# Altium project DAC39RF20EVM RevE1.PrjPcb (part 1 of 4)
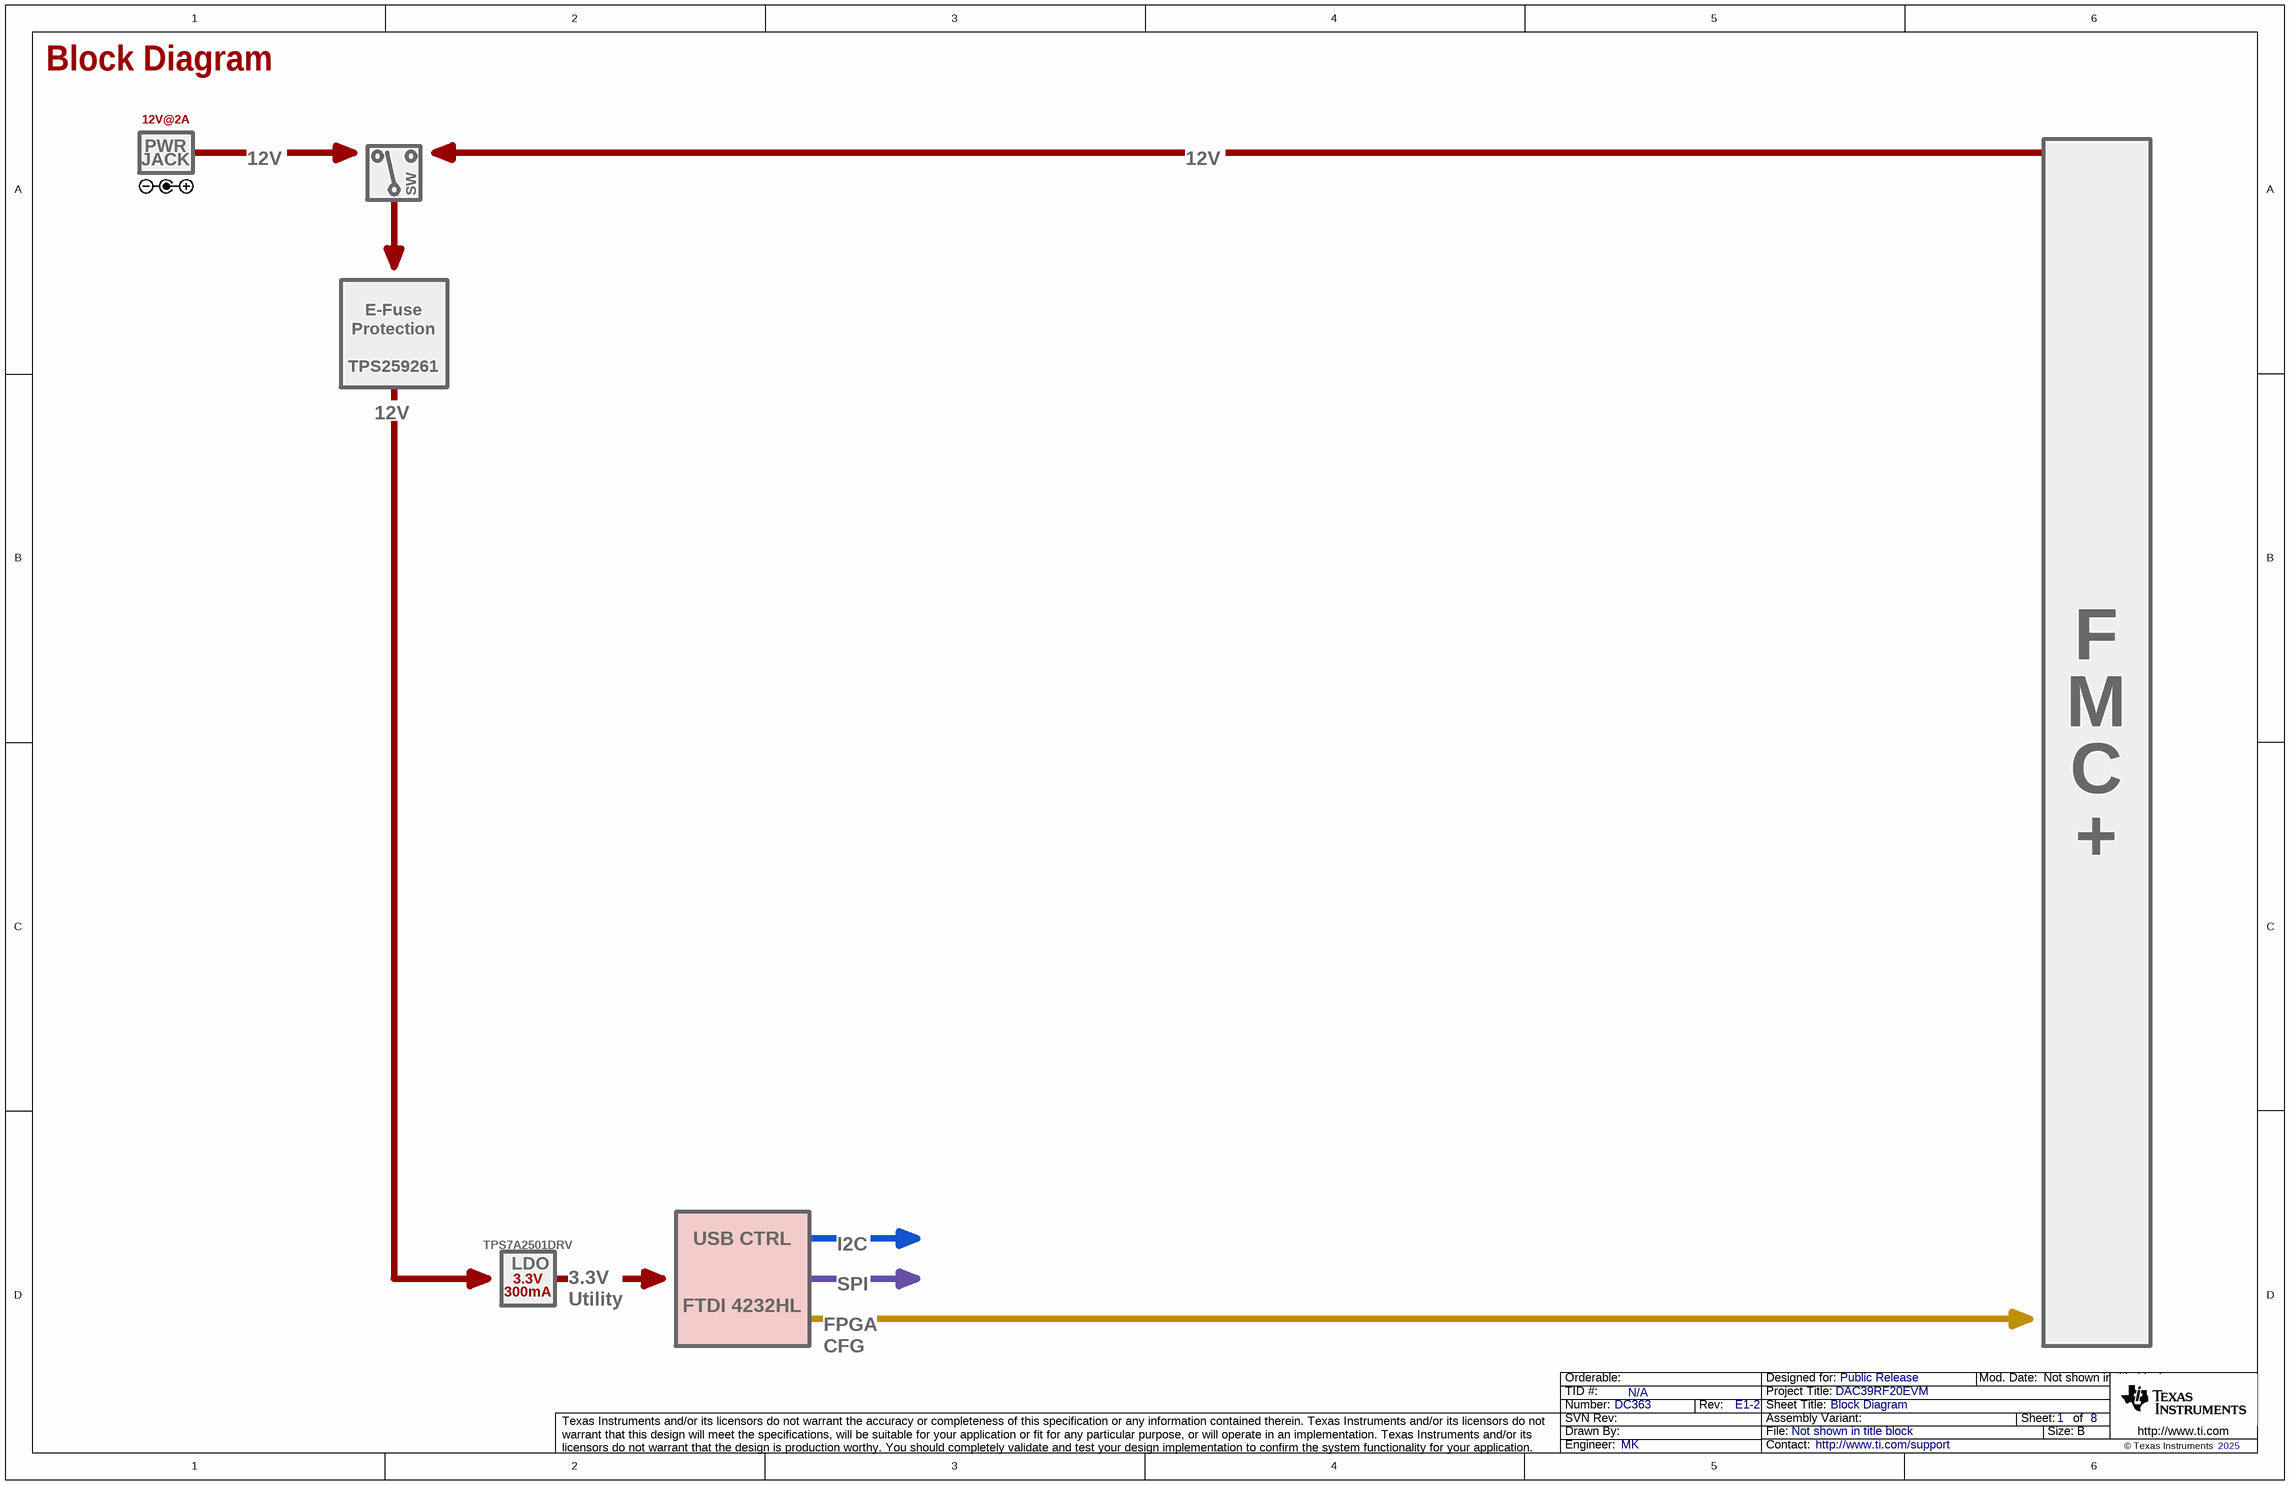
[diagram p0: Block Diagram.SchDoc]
TID: N/A; TechSupport: http://www.ti.com/support; SCH_Rev: E1-2; PRJ_Title: DAC39RF20EVM; PRJ_Number: DC363; PRJ_Engineer: MK; PRJ_Customer: Public Release; PCB_Rev: E1-2; PCB_Layout: GR; CopyrightYear: 2025
21 sheets, 789 parts. Net scope: flat (ports and power ports of the same name join across sheets).
Board file: DAC39RF20EVM.PcbDoc
Sheets:
  Block Diagram.SchDoc
  12V Input, Efuse and 3p3V Utility.SchDoc
  Power Sense ADC.SchDoc
  Power DC-DC Digital.SchDoc
  Power DC-DC Analog.SchDoc
  Power LDO 1p8V Analog.SchDoc
  Power LDO N1p8V Analog.SchDoc
  Power LDO 0p8V Analog.SchDoc
  Power LMK.SchDoc
  USB Control FTDI.SchDoc
  I2C & DAC LVL Shift and MUX.SchDoc
  LMK LVL Shift and Mux.SchDoc
  Clocking LMK04828.SchDoc
  DUT IO.SchDoc
  DUT Outputs.SchDoc
  DUT Power.SchDoc
  FMC+ Sections A-E.SchDoc
  FMC+ Sections F-H, J, K.SchDoc
  FMC+ Sections Y, Z, L, M.SchDoc
  Hardware & Mechanicals.SchDoc
  Revision History.SchDoc

## Sheet Block Diagram.SchDoc: Block Diagram
size 431 x 279 mm; Date: Not shown in title block; ApprovedBy: Not shown in title block; CheckedBy: Not shown in title block; Author: Not shown in title block; CompanyName: Not shown in title block; Engineer: Not shown in title block; Organization: Not shown in title block; Address1: Not shown in title block; Address2: Not shown in title block; Address3: Not shown in title block; Address4: Not shown in title block; DocumentNumber: 1; Revision: Use project parameter SCH_Rev; SheetNumber: 1; SheetTotal: 8; PageSetup: Record=PageOptions¦CenterHorizontal=True¦CenterVertical=True¦PrintScale=1.00¦XCorrection=1.00¦YCorrection=1.00¦PrintKind=0¦BorderSize=5000000¦LeftOffset=0¦BottomOffset=0¦Orientation=2¦PaperLength=1000¦PaperWidth=1000¦Scale=100¦PaperSource=15¦PrintQuality=600¦MediaType=1¦DitherType=10¦PaperKind=Letter¦PrintScaleMode=1

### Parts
(Parts that share a designator on the sheet are numbered #1, #2 ... from top to bottom, then left to right.)
*#1  FMC+  (value not drawn)  (graphical)
*#2  FTDI 4232HL  (value not drawn)  (graphical)
*?#1  PartNum: 12V@2A  (hidden comment: Power Jack)  (graphical)
*?#2  SWITCH  (value not drawn)  (graphical)
*?#3  E-Fuse  (value not drawn)  (graphical)
*?#4  A_Value: 300mA  V_Value: 3.3V  PartNum: TPS7A2501DRV  (hidden comment: LDO)  (graphical)

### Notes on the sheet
- 12V
- I2C
- SPI
- (near *?#4) 3.3V
  Utility
- FPGA
  CFG

## Sheet 12V Input, Efuse and 3p3V Utility.SchDoc: 12V Input & 3.3V Utility
size 431 x 279 mm; Date: Not shown in title block; ApprovedBy: Not shown in title block; CheckedBy: Not shown in title block; Author: Not shown in title block; CompanyName: Not shown in title block; Engineer: Not shown in title block; Organization: Not shown in title block; Address1: Not shown in title block; Address2: Not shown in title block; Address3: Not shown in title block; Address4: Not shown in title block; DocumentNumber: 1; Revision: Use project parameter SCH_Rev; SheetNumber: 2; SheetTotal: 21; PageSetup: Record=PageOptions¦CenterHorizontal=True¦CenterVertical=True¦PrintScale=1.00¦XCorrection=1.00¦YCorrection=1.00¦PrintKind=0¦BorderSize=5000000¦LeftOffset=0¦BottomOffset=0¦Orientation=2¦PaperLength=1000¦PaperWidth=1000¦Scale=100¦PaperSource=15¦PrintQuality=600¦MediaType=1¦DitherType=10¦PaperKind=Letter¦PrintScaleMode=1
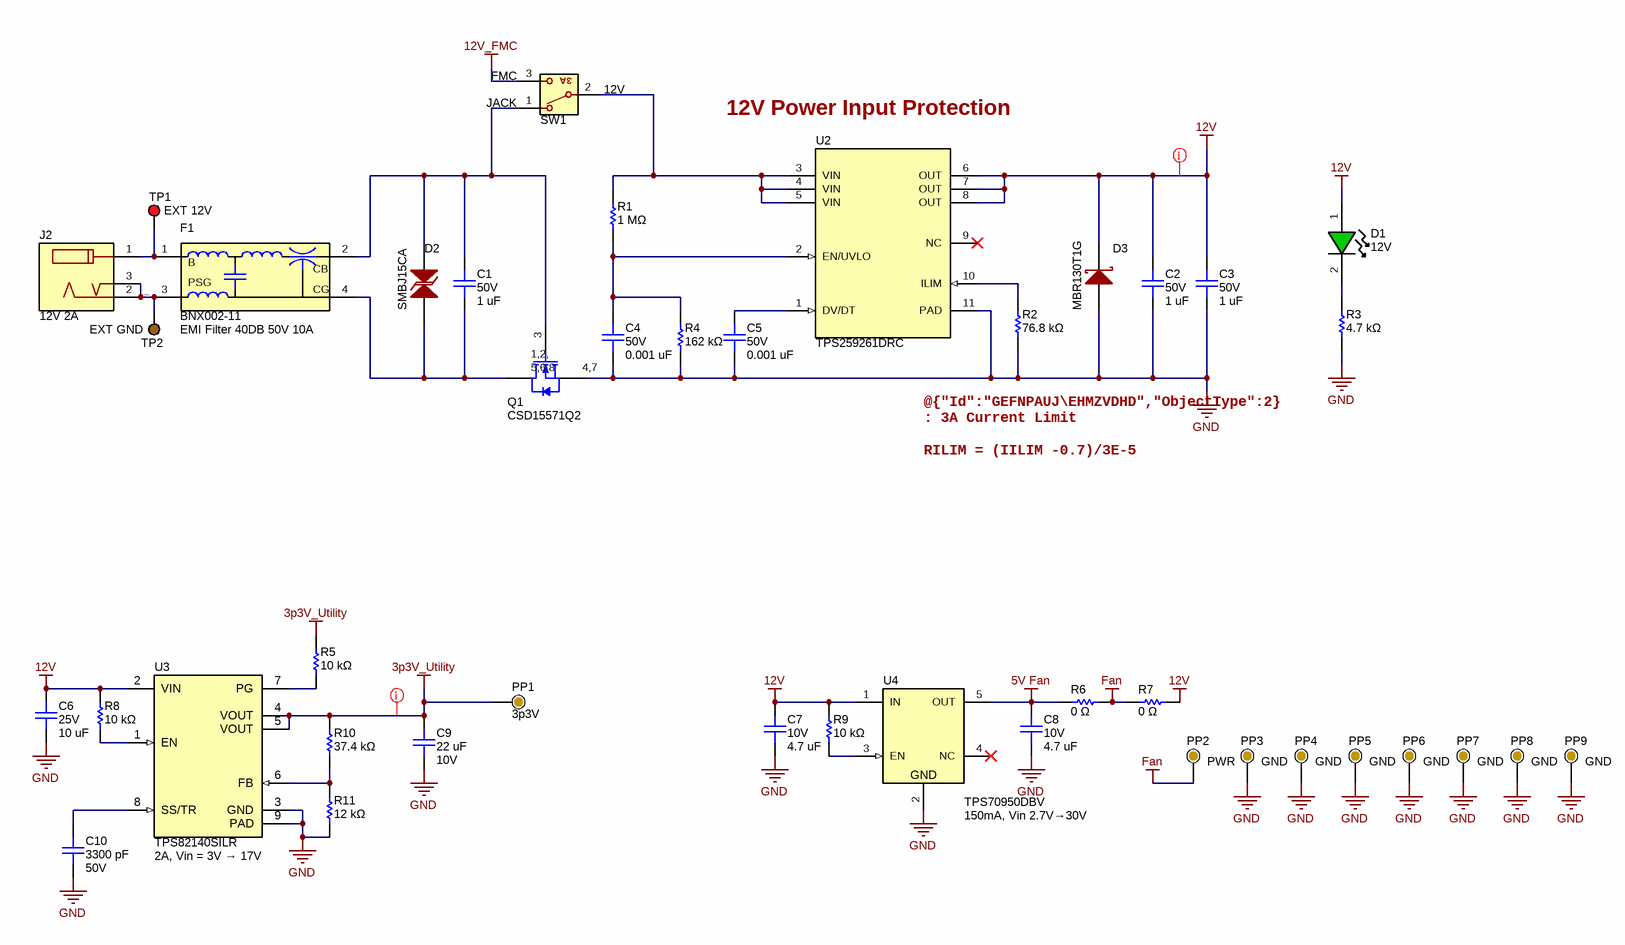
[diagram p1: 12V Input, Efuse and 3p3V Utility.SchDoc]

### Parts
C1  value 1 uF  Voltage - Rated: 50V  [0805L_cap]  (hidden comment: C2012X7R1H105K125AB)
C2  value 1 uF  Voltage - Rated: 50V  [0805L_cap]  (hidden comment: C2012X7R1H105K125AB)
C3  value 1 uF  Voltage - Rated: 50V  [0805L_cap]  (hidden comment: C2012X7R1H105K125AB)
C4  value 0.001 uF  Voltage - Rated: 50V  [0603L_cap]  (hidden comment: CGA3E2X7R1H102K080AA)
C5  value 0.001 uF  Voltage - Rated: 50V  [0603L_cap]  (hidden comment: CGA3E2X7R1H102K080AA)
C6  value 10 uF  Voltage - Rated: 25V  [0805L_cap]  (hidden comment: 08053D106KAT4A)
C7  value 4.7 uF  Voltage - Rated: 10V  [0402L_cap]  (hidden comment: C1005X5R1A475K050BC)
C8  value 4.7 uF  Voltage - Rated: 10V  [0402L_cap]  (hidden comment: C1005X5R1A475K050BC)
C9  value 22 uF  Voltage - Rated: 10V  [0805L_cap]  (hidden comment: C2012X7S1A226M125AC)
C10  value 3300 pF  Voltage - Rated: 50V  [0402L_cap]  (hidden comment: CGA2B2X7R1H332K050BA)
D1  Text1: 12V  [LED_LTST-C190-Green]  (hidden comment: LTST-C191TGKT)
D2  SMBJ15CA  [SMBJ15CA]
D3  MBR130T1G  [SOD-123]
F1  BNX002-11  Text1: EMI Filter 40DB 50V 10A  [FIL_BNX002-11]
J2  Text1: 12V 2A  [RAPC722X]  (hidden comment: RAPC722X)
PP1  Text1: 3p3V  [ProbePoint_TH_40mil]  (hidden comment: Probe Point)  (no BOM)
PP2  Text1: PWR  [ProbePoint_TH_40mil]  (hidden comment: Probe Point)  (no BOM)
PP3  Text1: GND  [ProbePoint_TH_40mil]  (hidden comment: Probe Point)  (no BOM)
PP4  Text1: GND  [ProbePoint_TH_40mil]  (hidden comment: Probe Point)  (no BOM)
PP5  Text1: GND  [ProbePoint_TH_40mil]  (hidden comment: Probe Point)  (no BOM)
PP6  Text1: GND  [ProbePoint_TH_40mil]  (hidden comment: Probe Point)  (no BOM)
PP7  Text1: GND  [ProbePoint_TH_40mil]  (hidden comment: Probe Point)  (no BOM)
PP8  Text1: GND  [ProbePoint_TH_40mil]  (hidden comment: Probe Point)  (no BOM)
PP9  Text1: GND  [ProbePoint_TH_40mil]  (hidden comment: Probe Point)  (no BOM)
Q1  CSD15571Q2  [DQK0006C]
R1  value 1 MΩ  [0402L]  (hidden comment: ERJ-2RKF1004X)
R2  value 76.8 kΩ  [0402L]  (hidden comment: ERJ-2RKF7682X)
R3  value 4.7 kΩ  [0805L]  (hidden comment: ERJ-6ENF4701V)
R4  value 162 kΩ  [0402L]  (hidden comment: ERJ-2RKF1623X)
R5  value 10 kΩ  [0402L]  (hidden comment: ERJ-2RKF1002X)
R6  value 0 Ω  [0805L]  (hidden comment: ERJ-6GEY0R00V)
R7  value 0 Ω  [0805L]  (hidden comment: ERJ-6GEY0R00V)
R8  value 10 kΩ  [0402L]  (hidden comment: ERJ-2RKF1002X)
R9  value 10 kΩ  [0402L]  (hidden comment: ERJ-2RKF1002X)
R10  value 37.4 kΩ  [0402L]  (hidden comment: ERA-2AEB3742X)
R11  value 12 kΩ  [0402L]  (hidden comment: ERJ-2RKF1202X)
SW1  Text1: JACK  Text2: 12V  Text3: FMC  [500ASSP1M2QE]  (hidden comment: 500ASSP1M2QE)
TP1  Text1: EXT 12V  [Keystone5010]  (hidden comment: 5010)
TP2  Text1: EXT GND  [Keystone5125]  (hidden comment: 5125)
U2  TPS259261DRC  [DRC0010J]
U3  TPS82140SILR  Text1: 2A, Vin = 3V → 17V  [SIL0008D]
U4  TPS70950DBV  Text1: 150mA, Vin 2.7V→30V  [DBV0005A]

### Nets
3p3V_Utility: C9.2 PP1.1 R5.2 R10.2 U3.4(VOUT) U3.5(VOUT)
5V Fan: C8.2 R6.2 U4.5(OUT)
12V: C2.2 C3.2 C6.2 C7.2 D1.1(A) D3.1(K) R7.1 R8.2 R9.2 U2.6(OUT) U2.7(OUT) U2.8(OUT) U3.2(VIN) U4.1(IN)
12V_FMC: SW1.3
Fan: PP2.1 R6.1 R7.2
GND: C2.1 C3.1 C4.1 C5.1 C6.1 C7.1 C8.1 C9.1 C10.1 D3.2(A) PP3.1 PP4.1 PP5.1 PP6.1 PP7.1 PP8.1 PP9.1 Q1.4,7(S) R2.1 R3.1 R4.1 R11.1 U2.11(PAD) U3.3(GND) U3.9(PAD) U4.2(GND)
EXTGND: F1.3(PSG) J2.2 J2.3 TP2.1
NetC1_1: C1.1 D2.2 F1.2(CB) Q1.3(G) SW1.1
NetC1_2: C1.2 D2.1 F1.4(CG) Q1.1,2,5,6,8(D)
NetC4_2: C4.2 R1.1 R4.2 U2.2(EN/UVLO)
NetC5_2: C5.2 U2.1(DV/DT)
NetC10_2: C10.2 U3.8(SS/TR)
NetD1_2: D1.2(K) R3.2
NetF1_1: F1.1(B) J2.1 TP1.1
NetR1_2: R1.2 SW1.2(COMM) U2.3(VIN) U2.4(VIN) U2.5(VIN)
NetR2_2: R2.2 U2.10(ILIM)
NetR5_1: R5.1 U3.7(PG)
NetR8_1: R8.1 U3.1(EN)
NetR9_1: R9.1 U4.3(EN)
NetR10_1: R10.1 R11.2 U3.6(FB)

Not connected (* = marked no-connect by the designer): U2 9(NC)*; U4 4(NC)*

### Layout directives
net class Power; net class GenPwr: 3p3V_Utility, 12V

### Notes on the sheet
- 12V Power Input Protection
- @{"Id":"GEFNPAUJ\EHMZVDHD","ObjectType":2} : 3A Current Limit
  RILIM = (IILIM -0.7)/3E-5

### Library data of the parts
C1-C3 = capcc02687: CAP CER 1UF 50V X7R 0805; Manufacturer: TDK Corporation; CompType: Capacitor Ceramic; Tolerance: ±10%; SizeX_mm: 2; SizeY_mm: 1.25; SizeZ_mm: 1.45
C4 C5 = capcc03751: CAP CER 1000PF 50V X7R 0603; Manufacturer: TDK Corporation; CompType: Capacitor Ceramic; Tolerance: ±10%; SizeX_mm: 1.6; SizeY_mm: 0.8; SizeZ_mm: 0.9
C6 = capcc03515: CAP CER 10UF 25V X5R 0805; Manufacturer: KYOCERA AVX; CompType: Capacitor Ceramic; Tolerance: ±10%; SizeX_mm: 2.01; SizeY_mm: 1.25; SizeZ_mm: 1.52
C7 C8 = capcc03298: CAP CER 4.7UF 10V X5R 0402; Manufacturer: TDK Corporation; CompType: Capacitor Ceramic; Tolerance: ±10%; SizeX_mm: 1; SizeY_mm: 0.5; SizeZ_mm: 0.65
C9 = capcc09395: CAP CER 22UF 10V X7S 0805; Manufacturer: TDK Corporation; CompType: Capacitor Ceramic; Tolerance: ±20%; SizeX_mm: 2; SizeY_mm: 1.25; SizeZ_mm: 1.45
C10 = capcc04738: CAP CER 3300PF 50V X7R 0402; Manufacturer: TDK Corporation; CompType: Capacitor Ceramic; Tolerance: ±10%; SizeX_mm: 1; SizeY_mm: 0.5; SizeZ_mm: 0.55
D1 = cmp00247: LED GREEN CLEAR CHIP SMD; Manufacturer: Lite-On Inc.; Current Rating (Amps): 20mA; Voltage - Forward (Vf) (Typ): 3.2V; SizeX_mm: 1.6; SizeY_mm: 0.8; SizeZ_mm: 0.65
D2 = cmp00440: 24.4V Clamp 24.6A Ipp Tvs Diode; Manufacturer: Littlefuse; CompType: Diode TVS
D3 = cmp00438: DIODE SCHOTTKY 30V 1A SOD123; Manufacturer: Onsemi; Alt PartNumber: RB160M-30TR; Alt Manufacturer: Rohm Semiconductor
F1 = cmp00325: EMI Filter Circuits 40 DB 50V 10A; Manufacturer: Murata Electronics
J2 = cmp00022: Power Jack, mini, 2.1mm OD, R/A, TH; Manufacturer: Switchcraft
PP1-PP9 = Probe Point: Probe Point that can be used in lue of a test point; UniqueID: cmp00025
Q1 = cmp00159: MOSFET, N-CH, 20 V, 10 A; Manufacturer: Texas Instruments; CompType: FET
R1 = RSMD040200026: RES SMD 1M OHM 1% 1/10W 0402; Manufacturer: Panasonic Electronic Components; CompType: Resistor SMD; Power (Watts): 0.1W, 1/10W; Temperature Coefficient: ±100ppm/°C; SizeX_mm: 1; SizeY_mm: 0.5; SizeZ_mm: 0.4
R2 = RSMD040203665: RES SMD 76.8K OHM 1% 1/10W 0402; Manufacturer: Panasonic Electronic Components; CompType: Resistor SMD; Power (Watts): 0.1W, 1/10W; Temperature Coefficient: ±100ppm/°C; SizeX_mm: 1; SizeY_mm: 0.5; SizeZ_mm: 0.4
R3 = RSMD080501129: RES SMD 4.7K OHM 1% 1/8W 0805; Manufacturer: Panasonic Electronic Components; CompType: Resistor SMD; Power (Watts): 0.125W, 1/8W; Temperature Coefficient: ±100ppm/°C; SizeX_mm: 2; SizeY_mm: 1.25; SizeZ_mm: 0.7
R4 = RSMD040200945: RES SMD 162K OHM 1% 1/10W 0402; Manufacturer: Panasonic Electronic Components; CompType: Resistor SMD; Power (Watts): 0.1W, 1/10W; Temperature Coefficient: ±100ppm/°C; SizeX_mm: 1; SizeY_mm: 0.5; SizeZ_mm: 0.4
R5 R8 R9 = RSMD040200314: RES SMD 10K OHM 1% 1/10W 0402; Manufacturer: Panasonic Electronic Components; CompType: Resistor SMD; Power (Watts): 0.1W, 1/10W; Temperature Coefficient: ±100ppm/°C; SizeX_mm: 1; SizeY_mm: 0.5; SizeZ_mm: 0.4
R6 R7 = RSMD080510615: RES SMD 0 OHM JUMPER 1/8W 0805; Manufacturer: Panasonic Electronic Components; CompType: Resistor SMD; Power (Watts): 0.125W, 1/8W; SizeX_mm: 2; SizeY_mm: 1.25; SizeZ_mm: 0.7
R10 = RSMD040202418: RES SMD 37.4KOHM 0.1% 1/16W 0402; Manufacturer: Panasonic Electronic Components; CompType: Resistor SMD; Power (Watts): 0.063W, 1/16W; Temperature Coefficient: ±25ppm/°C; SizeX_mm: 1; SizeY_mm: 0.5; SizeZ_mm: 0.4
R11 = RSMD040200519: RES SMD 12K OHM 1% 1/10W 0402; Manufacturer: Panasonic Electronic Components; CompType: Resistor SMD; Power (Watts): 0.1W, 1/10W; Temperature Coefficient: ±100ppm/°C; SizeX_mm: 1; SizeY_mm: 0.5; SizeZ_mm: 0.4
SW1 = cmp00460: SWITCH SLIDE SPDT 3A 120V; Manufacturer: E-Switch; Pitch (mm): 2.54
TP1 = cmp00040: Test Point, Multipurpose, Red, TH; Manufacturer: Keystone
TP2 = cmp00047: Test Point, Multipurpose, Brown, TH; Manufacturer: Keystone
U2 = cmp00157: 12V, 5A, 30mΩ eFuse with Adjustable +/-15% Accurate Current Limit, DRC0010J (VSON-10); Manufacturer: Texas Instruments
U3 = TPS82140SILR: 17V Input 2A Synchronous Step-Down Converter MicroSiP Module With Integrated Inductor, SIL0008D (uSIP-8); Manufacturer: Texas Instruments; Alternate PartNumber: TPS82140SILT; CompType: Switcher
U4 = TPS70950DBV: 150-mA, 30-V, ultra-low-IQ, low-dropout voltage regulator with reverse current protection and enable; Manufacturer: Texas Instruments; CompType: LDO

## Sheet Power Sense ADC.SchDoc: Sense ADC
size 431 x 279 mm; Date: Not shown in title block; ApprovedBy: Not shown in title block; CheckedBy: Not shown in title block; Author: Not shown in title block; CompanyName: Not shown in title block; Engineer: Not shown in title block; Organization: Not shown in title block; Address1: Not shown in title block; Address2: Not shown in title block; Address3: Not shown in title block; Address4: Not shown in title block; DocumentNumber: 1; Revision: Use project parameter SCH_Rev; SheetNumber: 3; SheetTotal: 21; PageSetup: Record=PageOptions¦CenterHorizontal=True¦CenterVertical=True¦PrintScale=1.00¦XCorrection=1.00¦YCorrection=1.00¦PrintKind=0¦BorderSize=5000000¦LeftOffset=0¦BottomOffset=0¦Orientation=2¦PaperLength=1000¦PaperWidth=1000¦Scale=100¦PaperSource=15¦PrintQuality=600¦MediaType=1¦DitherType=10¦PaperKind=Letter¦PrintScaleMode=1
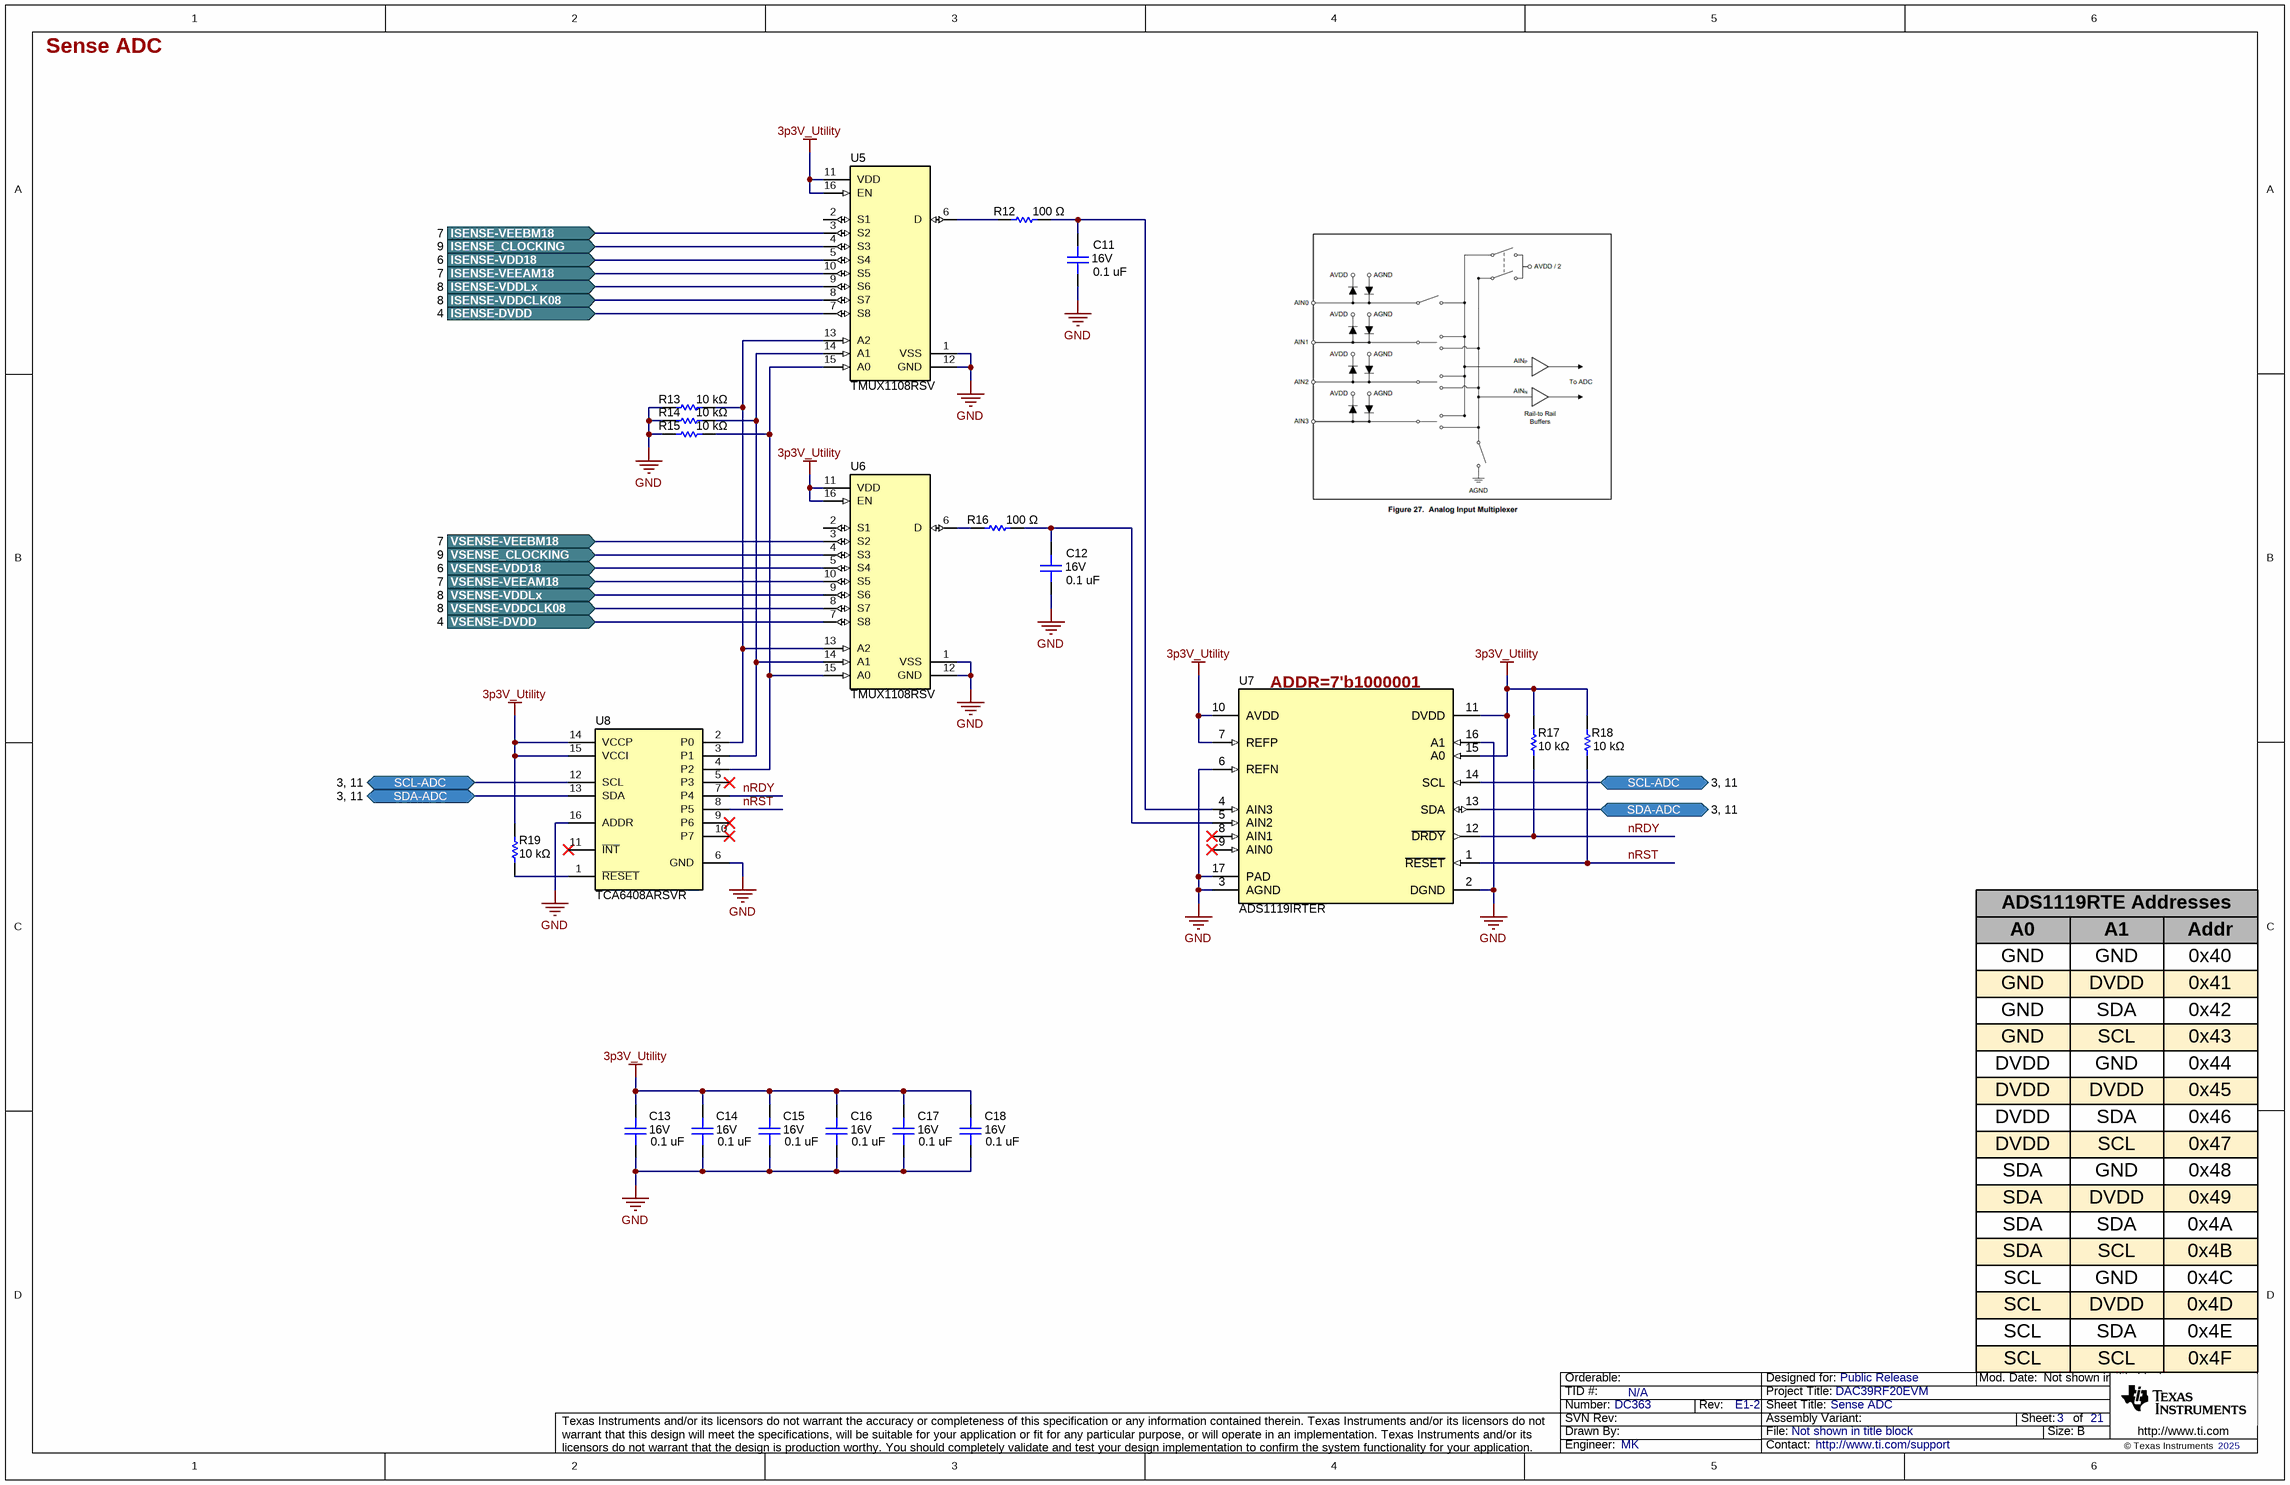
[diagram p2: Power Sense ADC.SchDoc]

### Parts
C11  value 0.1 uF  Voltage - Rated: 16V  [0201_cap]  (hidden comment: C0603X5R1C104K030BC)
C12  value 0.1 uF  Voltage - Rated: 16V  [0201_cap]  (hidden comment: C0603X5R1C104K030BC)
C13  value 0.1 uF  Voltage - Rated: 16V  [0201_cap]  (hidden comment: C0603X5R1C104K030BC)
C14  value 0.1 uF  Voltage - Rated: 16V  [0201_cap]  (hidden comment: C0603X5R1C104K030BC)
C15  value 0.1 uF  Voltage - Rated: 16V  [0201_cap]  (hidden comment: C0603X5R1C104K030BC)
C16  value 0.1 uF  Voltage - Rated: 16V  [0201_cap]  (hidden comment: C0603X5R1C104K030BC)
C17  value 0.1 uF  Voltage - Rated: 16V  [0201_cap]  (hidden comment: C0603X5R1C104K030BC)
C18  value 0.1 uF  Voltage - Rated: 16V  [0201_cap]  (hidden comment: C0603X5R1C104K030BC)
R12  value 100 Ω  [0201]  (hidden comment: ERJ-1GNF1000C)
R13  value 10 kΩ  [0201]  (hidden comment: ERJ-1GNF1002C)
R14  value 10 kΩ  [0201]  (hidden comment: ERJ-1GNF1002C)
R15  value 10 kΩ  [0201]  (hidden comment: ERJ-1GNF1002C)
R16  value 100 Ω  [0201]  (hidden comment: ERJ-1GNF1000C)
R17  value 10 kΩ  [0201]  (hidden comment: ERJ-1GNF1002C)
R18  value 10 kΩ  [0201]  (hidden comment: ERJ-1GNF1002C)
R19  value 10 kΩ  [0201]  (hidden comment: ERJ-1GNF1002C)
U5  TMUX1108RSVR  [RSV0016A]  (value not drawn)
U6  TMUX1108RSVR  [RSV0016A]  (value not drawn)
U7  ADS1119IRTET  [RTE0016D]  (value not drawn)
U8  TCA6408ARSVR  [RSV0016A]

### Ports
ISENSE-DVDD (in, see 4), ISENSE-VDD18 (in, see 6), ISENSE-VDDCLK08 (in, see 8), ISENSE-VDDLx (in, see 8), ISENSE-VEEAM18 (in, see 7), ISENSE-VEEBM18 (in, see 7), ISENSE_CLOCKING (in, see 9), SCL-ADC (bidir, see 3, 11), SDA-ADC (bidir, see 3, 11), VSENSE-DVDD (in, see 4), VSENSE-VDD18 (in, see 6), VSENSE-VDDCLK08 (in, see 8), VSENSE-VDDLx (in, see 8), VSENSE-VEEAM18 (in, see 7), VSENSE-VEEBM18 (in, see 7), VSENSE_CLOCKING (in, see 9)

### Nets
3p3V_Utility: C13.1 C14.1 C15.1 C16.1 C17.1 C18.1 R17.2 R18.2 R19.2 U5.11(VDD) U5.16(EN) U6.11(VDD) U6.16(EN) U7.7(REFP) U7.10(AVDD) U7.11(DVDD) U7.15(A0) U8.14(VCCP) U8.15(VCCI)
GND: C11.2 C12.2 C13.2 C14.2 C15.2 C16.2 C17.2 C18.2 R13.2 R14.2 R15.2 U5.1(VSS) U5.12(GND) U6.1(VSS) U6.12(GND) U7.2(DGND) U7.3(AGND) U7.6(REFN) U7.16(A1) U7.17(PAD) U8.6(GND) U8.16(ADDR)
ISENSE-DVDD: U5.7(S8) ; port ISENSE-DVDD
ISENSE-VDD18: U5.5(S4) ; port ISENSE-VDD18
ISENSE-VDDCLK08: U5.8(S7) ; port ISENSE-VDDCLK08
ISENSE-VDDLx: U5.9(S6) ; port ISENSE-VDDLx
ISENSE-VEEAM18: U5.10(S5) ; port ISENSE-VEEAM18
ISENSE-VEEBM18: U5.3(S2) ; port ISENSE-VEEBM18
ISENSE_CLOCKING: U5.4(S3) ; port ISENSE_CLOCKING
nRDY: R17.1 U7.12(~{DRDY}) U8.7(P4)
nRST: R18.1 U7.1(~{RESET}) U8.8(P5)
SCL-ADC: U7.14(SCL) U8.12(SCL) ; port SCL-ADC
SDA-ADC: U7.13(SDA) U8.13(SDA) ; port SDA-ADC
VSENSE-DVDD: U6.7(S8) ; port VSENSE-DVDD
VSENSE-VDD18: U6.5(S4) ; port VSENSE-VDD18
VSENSE-VDDCLK08: U6.8(S7) ; port VSENSE-VDDCLK08
VSENSE-VDDLx: U6.9(S6) ; port VSENSE-VDDLx
VSENSE-VEEAM18: U6.10(S5) ; port VSENSE-VEEAM18
VSENSE-VEEBM18: U6.3(S2) ; port VSENSE-VEEBM18
VSENSE_CLOCKING: U6.4(S3) ; port VSENSE_CLOCKING
NetC11_1: C11.1 R12.2 U7.4(AIN3)
NetC12_1: C12.1 R16.2 U7.5(AIN2)
NetR12_1: R12.1 U5.6(D)
NetR13_1: R13.1 U5.13(A2) U6.13(A2) U8.2(P0)
NetR14_1: R14.1 U5.14(A1) U6.14(A1) U8.3(P1)
NetR15_1: R15.1 U5.15(A0) U6.15(A0) U8.4(P2)
NetR16_1: R16.1 U6.6(D)
NetR19_1: R19.1 U8.1(~{RESET})

Not connected (* = marked no-connect by the designer): U5 2(S1); U6 2(S1); U7 8(AIN1)* 9(AIN0)*; U8 5(P3)* 9(P6)* 10(P7)* 11(~{INT})*

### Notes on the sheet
- (near U7) ADDR=7'b1000001
- A0
- GND
- ADS1119RTE Addresses
- A1
- Addr
- 0x40
- DVDD
- SDA
- 0x41
- 0x42
- SCL
- 0x43
- 0x44
- 0x45
- 0x46
- 0x47
- 0x48
- 0x49
- 0x4A
- 0x4B
- 0x4C
- 0x4D
- 0x4E
- 0x4F

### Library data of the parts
C11-C18 = capcc01389: CAP CER 0.1UF 16V X5R 0201; Manufacturer: TDK Corporation; SizeZ_mm: 0.33; SizeY_mm: 0.3; CompType: Capacitor Ceramic; SizeX_mm: 0.6; Tolerance: ±10%
R12 R16 = RSMD020100289: RES SMD 100 OHM 1% 1/20W 0201; Manufacturer: Panasonic Electronic Components; CompType: Resistor SMD; Power (Watts): 0.05W, 1/20W; Temperature Coefficient: ±200ppm/°C
R13-R15 R17-R19 = RSMD020100762: RES SMD 10K OHM 1% 1/20W 0201; Manufacturer: Panasonic Electronic Components; CompType: Resistor SMD; Power (Watts): 0.05W, 1/20W; Temperature Coefficient: ±200ppm/°C
U5 U6 = TMUX1108RSV: 3-pA on-state leakage current, 5-V, 8:1, 1-channel precision multiplexer; Manufacturer: Texas Instruments; CompType: MUX; SizeZ_mm: .55; SizeY_mm: 2.6; SizeX_mm: 1.8
U7 = ADS1119IRTER: 16-Bit, 4-Channel, 1-kSPS, Delta-Sigma ADC with I2C Interface, RTE0016D (WQFN-16); Alternate Manufacturer: Texas Instruments; SizeAreaWB_mm2: 16; SizeZ_mm: 0.8; SizeX_mm: 3; SizeArea_mm2: 9; AEC Qualified: N; AEC Category: Q200
U8 = cmp00387: 8-bit translating 1.65- to 5.5-V I2C/SMBus I/O expander with interrupt, reset & config registers; Manufacturer: Texas Instruments; CompType: IO Expander

## Sheet Power DC-DC Digital.SchDoc: DAC DVDD Rail
size 431 x 279 mm; Date: Not shown in title block; ApprovedBy: Not shown in title block; CheckedBy: Not shown in title block; Author: Not shown in title block; CompanyName: Not shown in title block; Engineer: Not shown in title block; Organization: Not shown in title block; Address1: Not shown in title block; Address2: Not shown in title block; Address3: Not shown in title block; Address4: Not shown in title block; DocumentNumber: 1; Revision: Use project parameter SCH_Rev; SheetNumber: 4; SheetTotal: 21; PageSetup: Record=PageOptions¦CenterHorizontal=True¦CenterVertical=True¦PrintScale=1.00¦XCorrection=1.00¦YCorrection=1.00¦PrintKind=0¦BorderSize=5000000¦LeftOffset=0¦BottomOffset=0¦Orientation=2¦PaperLength=1000¦PaperWidth=1000¦Scale=100¦PaperSource=15¦PrintQuality=600¦MediaType=1¦DitherType=10¦PaperKind=Letter¦PrintScaleMode=1
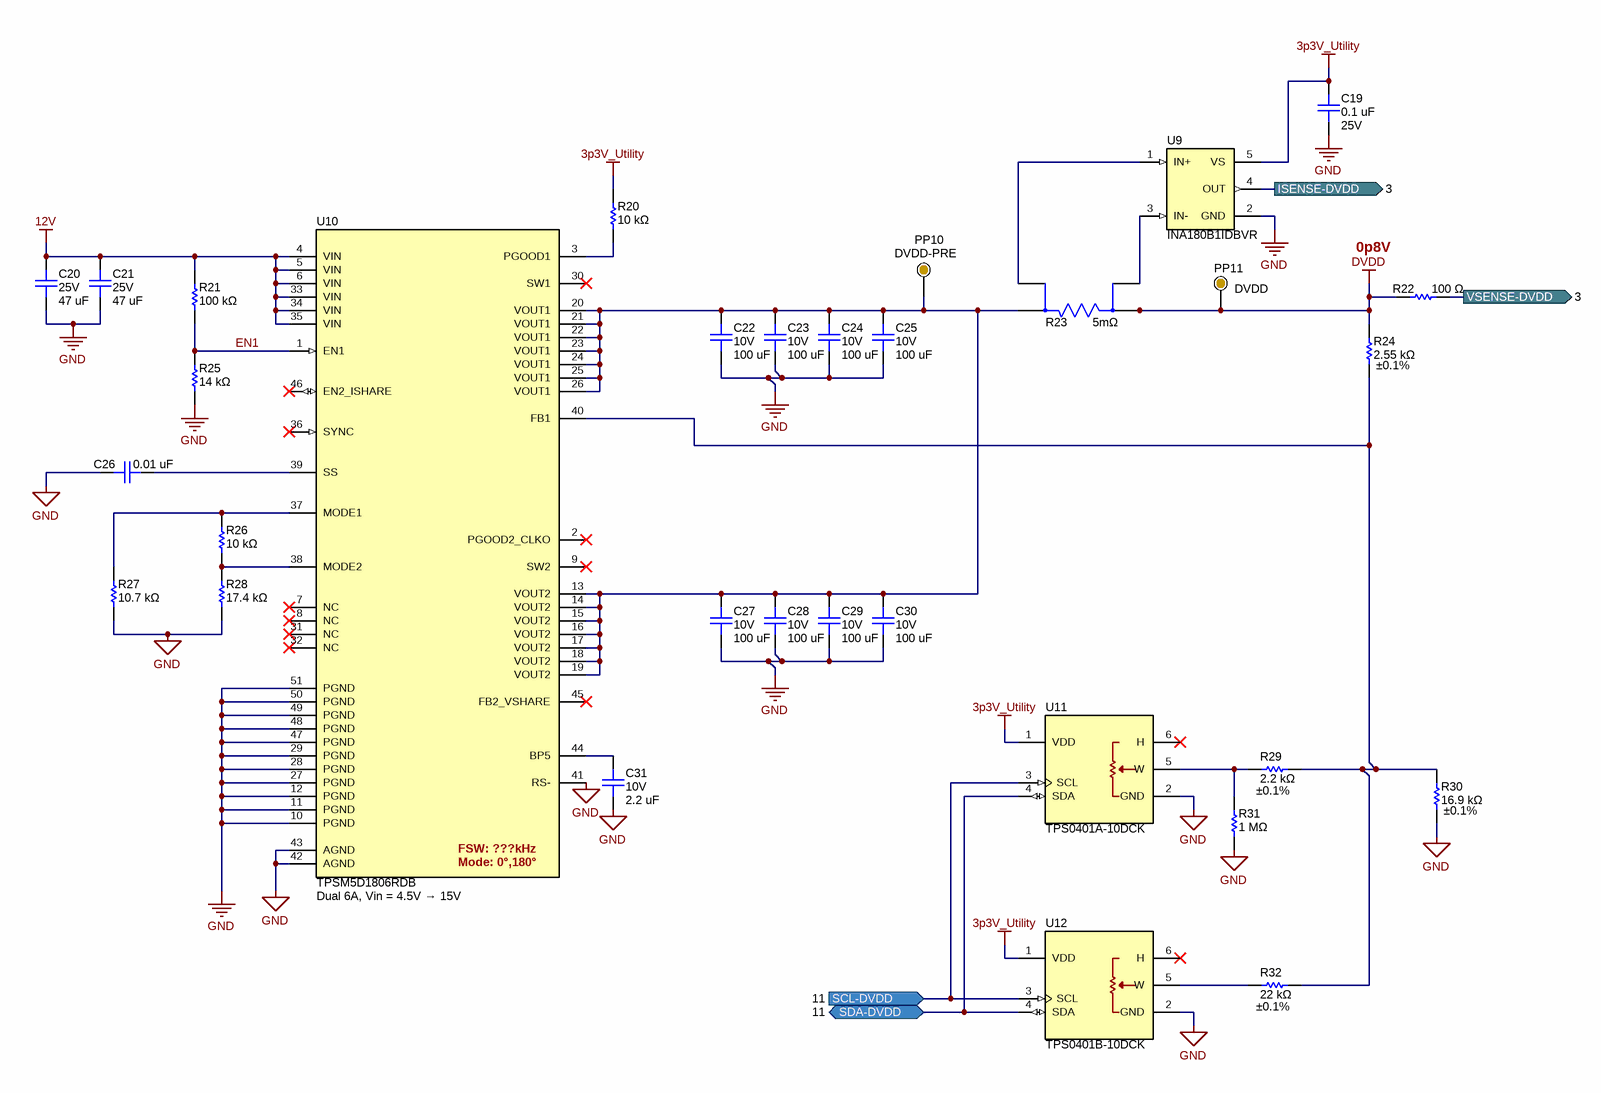
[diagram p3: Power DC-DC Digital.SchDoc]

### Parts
C19  value 0.1 uF  Voltage - Rated: 25V  [0402L_cap]  (hidden comment: GRT155R71E104KE01J)
C20  value 47 uF  Voltage - Rated: 25V  [1206L_cap]  (hidden comment: C3216X5R1E476M160AC)
C21  value 47 uF  Voltage - Rated: 25V  [1206L_cap]  (hidden comment: C3216X5R1E476M160AC)
C22  value 100 uF  Voltage - Rated: 10V  [1206L_cap]  (hidden comment: GMC31X5R107M10NT)
C23  value 100 uF  Voltage - Rated: 10V  [1206L_cap]  (hidden comment: GMC31X5R107M10NT)
C24  value 100 uF  Voltage - Rated: 10V  [1206L_cap]  (hidden comment: GMC31X5R107M10NT)
C25  value 100 uF  Voltage - Rated: 10V  [1206L_cap]  (hidden comment: GMC31X5R107M10NT)
C26  value 0.01 uF  [0402L_cap]  (hidden comment: 0402YD103KAT2A)
C27  value 100 uF  Voltage - Rated: 10V  [1206L_cap]  (hidden comment: GMC31X5R107M10NT)
C28  value 100 uF  Voltage - Rated: 10V  [1206L_cap]  (hidden comment: GMC31X5R107M10NT)
C29  value 100 uF  Voltage - Rated: 10V  [1206L_cap]  (hidden comment: GMC31X5R107M10NT)
C30  value 100 uF  Voltage - Rated: 10V  [1206L_cap]  (hidden comment: GMC31X5R107M10NT)
C31  value 2.2 uF  Voltage - Rated: 10V  [0402L_cap]  (hidden comment: CM05X5R225K10AH)
PP10  Text1: DVDD-PRE  [ProbePoint_TH_40mil]  (hidden comment: Probe Point)  (no BOM)
PP11  Text1: DVDD  [ProbePoint_TH_40mil]  (hidden comment: Probe Point)  (no BOM)
R20  value 10 kΩ  [0402L]  (hidden comment: ERJ-2RKF1002X)
R21  value 100 kΩ  [0402L]  (hidden comment: ERJ-2RKF1003X)
R22  value 100 Ω  [0201]  (hidden comment: ERJ-1GNF1000C)
R23  Res_ohm: 5mΩ  [FP-KRL3216T4A-M-R005-F-T1_1206-MFG]  (hidden comment: KRL3216T4A-M-R005-F-T1)
R24  value 2.55 kΩ  Tolerance: ±0.1%  [0402L]  (hidden comment: ERA-2APB2551X)
R25  value 14 kΩ  [0402L]  (hidden comment: ERJ-2RKF1402X)
R26  value 10 kΩ  [0402L]  (hidden comment: ERJ-2RKF1002X)
R27  value 10.7 kΩ  [0402L]  (hidden comment: ERJ-2RKF1072X)
R28  value 17.4 kΩ  [0402L]  (hidden comment: ERJ-2RKF1742X)
R29  value 2.2 kΩ  Tolerance: ±0.1%  [0402L]  (hidden comment: ERA-2ARB222X)
R30  value 16.9 kΩ  Tolerance: ±0.1%  [0402L]  (hidden comment: ERA-2ARB1692X)
R31  value 1 MΩ  [0402L]  (hidden comment: ERJ-PA2F1004X)
R32  value 22 kΩ  Tolerance: ±0.1%  [0402L]  (hidden comment: ERA-2APB223X)
U9  INA180B1IDBVR  [DBV0005A]
U10  TPSM5D1806RDB  Text1: Dual 6A, Vin = 4.5V → 15V  Mode: 0°,180°  FSW: ???kHz  [RDB0051A]
U11  TPS0401A-10DCK  [DCK0006A]
U12  TPS0401B-10DCK  [DCK0006A]

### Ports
ISENSE-DVDD (out, see 3), SCL-DVDD (in, see 11), SDA-DVDD (bidir, see 11), VSENSE-DVDD (out, see 3)

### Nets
3p3V_Utility: C19.2 R20.2 U9.5(VS) U11.1(VDD) U12.1(VDD)
12V: C20.2 C21.2 R21.2 U10.4(VIN) U10.5(VIN) U10.6(VIN) U10.33(VIN) U10.34(VIN) U10.35(VIN)
DVDD: PP11.1 R22.1 R23.3(1_I) R24.2
GND: C19.1 C20.1 C21.1 C22.1 C23.1 C24.1 C25.1 C26.1 C27.1 C28.1 C29.1 C30.1 C31.1 R25.1 R27.1 R28.1 R30.2 R31.2 U9.2(GND) U10.10(PGND) U10.11(PGND) U10.12(PGND) U10.27(PGND) U10.28(PGND) U10.29(PGND) U10.41(RS-) U10.42(AGND) U10.43(AGND) U10.47(PGND) U10.48(PGND) U10.49(PGND) U10.50(PGND) U10.51(PGND) U11.2(GND) U12.2(GND)
EN1: R21.1 R25.2 U10.1(EN1)
ISENSE-DVDD: U9.4(OUT) ; port ISENSE-DVDD
SCL-DVDD: U11.3(SCL) U12.3(SCL) ; port SCL-DVDD
SDA-DVDD: U11.4(SDA) U12.4(SDA) ; port SDA-DVDD
VSENSE-DVDD: R22.2 ; port VSENSE-DVDD
NetC22_2: C22.2 C23.2 C24.2 C25.2 C27.2 C28.2 C29.2 C30.2 PP10.1 R23.4(2_I) U10.13(VOUT2) U10.14(VOUT2) U10.15(VOUT2) U10.16(VOUT2) U10.17(VOUT2) U10.18(VOUT2) U10.19(VOUT2) U10.20(VOUT1) U10.21(VOUT1) U10.22(VOUT1) U10.23(VOUT1) U10.24(VOUT1) U10.25(VOUT1) U10.26(VOUT1)
NetC26_2: C26.2 U10.39(SS)
NetC31_2: C31.2 U10.44(BP5)
NetR20_1: R20.1 U10.3(PGOOD1)
NetR23_1: R23.1(1_V) U9.3(IN-)
NetR23_2: R23.2(2_V) U9.1(IN+)
NetR24_1: R24.1 R29.2 R30.1 R32.2 U10.40(FB1)
NetR26_1: R26.1 R27.2 U10.37(MODE1)
NetR26_2: R26.2 R28.2 U10.38(MODE2)
NetR29_1: R29.1 R31.1 U11.5(W)
NetR32_1: R32.1 U12.5(W)

Not connected (* = marked no-connect by the designer): U10 2(PGOOD2_CLKO)* 7(NC)* 8(NC)* 9(SW2)* 30(SW1)* 31(NC)* 32(NC)* 36(SYNC)* 45(FB2_VSHARE)* 46(EN2_ISHARE)*; U11 6(H)*; U12 6(H)*

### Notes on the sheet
- (near R22) 0p8V

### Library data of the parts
C19 = capcc09401: CAP CER 0.1UF 25V X7R 0402; Manufacturer: Murata; CompType: Capacitor Ceramic; Tolerance: ±10%; SizeX_mm: 1; SizeY_mm: 0.5; SizeZ_mm: 0.7
C20 C21 = capcc09404: CAP CER 47UF 25V X5R 1206; Manufacturer: TDK Corporation; CompType: Capacitor Ceramic; Tolerance: ±20%; SizeX_mm: 3.2; SizeY_mm: 1.6; SizeZ_mm: 1.8
C22-C25 C27-C30 = capcc06824: CAP CER 100UF 10V X5R 1206; Manufacturer: CAL-CHIP ELECTRONICS, INC.; CompType: Capacitor Ceramic; Tolerance: ±20%; SizeX_mm: 3.2; SizeY_mm: 1.6
C26 = capcc05508: CAP CER 10000PF 16V X5R 0402; Manufacturer: KYOCERA AVX; CompType: Capacitor Ceramic; Tolerance: ±10%; SizeX_mm: 1; SizeY_mm: 0.5; SizeZ_mm: 0.56
C31 = capcc03230: CAP CER 2.2UF 10V X5R 0402; Manufacturer: KYOCERA AVX; CompType: Capacitor Ceramic; Tolerance: ±10%; SizeX_mm: 1; SizeY_mm: 0.5; SizeZ_mm: 0.55
PP10 PP11 = Probe Point: as PP1 on sheet 12V Input, Efuse and 3p3V Utility
R20 R26 = RSMD040200314: as R5 on sheet 12V Input, Efuse and 3p3V Utility
R21 = RSMD040200358: RES SMD 100K OHM 1% 1/10W 0402; Manufacturer: Panasonic Electronic Components; CompType: Resistor SMD; Power (Watts): 0.1W, 1/10W; Temperature Coefficient: ±100ppm/°C; SizeX_mm: 1; SizeY_mm: 0.5; SizeZ_mm: 0.4
R22 = RSMD020100289: as R12 on sheet Power Sense ADC
R23 = CMP-0089456-1: 5 mOhms ±1% 1W Chip Resistor Wide 1206 (3216 Metric), 0612 Automotive AEC-Q200, Current Sense Metal Foil; Manufacturer: Susumu; AEC Grade: Grade 0; SizeZ_mm: 0.7mm; AEC Qualified: Yes; TempCo: 50ppm/°C
R24 = RSMD040201279: RES SMD 2.55KOHM 0.1% 1/16W 0402; Manufacturer: Panasonic Electronic Components; CompType: Resistor SMD; Power (Watts): 0.063W, 1/16W; Temperature Coefficient: ±15ppm/°C; SizeX_mm: 1; SizeY_mm: 0.5; SizeZ_mm: 0.4
R25 = RSMD040200723: RES SMD 14K OHM 1% 1/10W 0402; Manufacturer: Panasonic Electronic Components; CompType: Resistor SMD; Power (Watts): 0.1W, 1/10W; Temperature Coefficient: ±100ppm/°C; SizeX_mm: 1; SizeY_mm: 0.5; SizeZ_mm: 0.4
R27 = RSMD040200350: RES SMD 10.7K OHM 1% 1/10W 0402; Manufacturer: Panasonic Electronic Components; CompType: Resistor SMD; Power (Watts): 0.1W, 1/10W; Temperature Coefficient: ±100ppm/°C; SizeX_mm: 1; SizeY_mm: 0.5; SizeZ_mm: 0.4
R28 = RSMD040200983: RES SMD 17.4K OHM 1% 1/10W 0402; Manufacturer: Panasonic Electronic Components; CompType: Resistor SMD; Power (Watts): 0.1W, 1/10W; Temperature Coefficient: ±100ppm/°C; SizeX_mm: 1; SizeY_mm: 0.5; SizeZ_mm: 0.4
R29 = RSMD040201204: RES SMD 2.2K OHM 0.1% 1/16W 0402; Manufacturer: Panasonic Electronic Components; CompType: Resistor SMD; Power (Watts): 0.063W, 1/16W; Temperature Coefficient: ±10ppm/°C; SizeX_mm: 1; SizeY_mm: 0.5; SizeZ_mm: 0.4
R30 = RSMD040200908: RES SMD 16.9KOHM 0.1% 1/16W 0402; Manufacturer: Panasonic Electronic Components; CompType: Resistor SMD; Power (Watts): 0.063W, 1/16W; Temperature Coefficient: ±10ppm/°C; SizeX_mm: 1; SizeY_mm: 0.5; SizeZ_mm: 0.4
R31 = RSMD040200022: RES SMD 1M OHM 1% 1/5W 0402; Manufacturer: Panasonic Electronic Components; CompType: Resistor SMD; Power (Watts): 0.2W, 1/5W; Temperature Coefficient: ±100ppm/°C; SizeX_mm: 1; SizeY_mm: 0.5; SizeZ_mm: 0.4
R32 = RSMD040201457: RES SMD 22K OHM 0.1% 1/16W 0402; Manufacturer: Panasonic Electronic Components; CompType: Resistor SMD; Power (Watts): 0.063W, 1/16W; Temperature Coefficient: ±15ppm/°C; SizeX_mm: 1; SizeY_mm: 0.5; SizeZ_mm: 0.4
U9 = INA180B1IDBVR: 26V, 350kHz current sense amplifier; Manufacturer: Texas Instruments; Alt PartNumber: INA180B1IDBVT; CompType: Current Amplifier
U10 = cmp00235: 4.5-V to 15-V Input, Dual 6-A / Single 12-A Output Power Module; Manufacturer: Texas Instruments; CompType: Switcher
U11 = cmp00230: 128-tap single-channel digital potentiometer (digipot) with I2C interface (address 0101110); Alternate PartNumber: TPL0401A-10DCKT; Manufacturer: Texas Instruments; SymbolCreator: Altium; SizeArea_mm2: 4.2; U/M: EA; SizeAreaWB_mm2: 9.3
U12 = cmp00231: 128-tap single-channel digital potentiometer (digipot) with I2C interface (address 0111110); Alternate PartNumber: TPL0401A-10DCKT; Manufacturer: Texas Instruments; SymbolCreator: Altium; SizeArea_mm2: 4.2; U/M: EA; SizeAreaWB_mm2: 9.3

## Sheet Power DC-DC Analog.SchDoc: DAC Analog Switchers
size 431 x 279 mm; Date: Not shown in title block; ApprovedBy: Not shown in title block; CheckedBy: Not shown in title block; Author: Not shown in title block; CompanyName: Not shown in title block; Engineer: Not shown in title block; Organization: Not shown in title block; Address1: Not shown in title block; Address2: Not shown in title block; Address3: Not shown in title block; Address4: Not shown in title block; DocumentNumber: 1; Revision: Use project parameter SCH_Rev; SheetNumber: 5; SheetTotal: 21; PageSetup: Record=PageOptions¦CenterHorizontal=True¦CenterVertical=True¦PrintScale=1.00¦XCorrection=1.00¦YCorrection=1.00¦PrintKind=0¦BorderSize=5000000¦LeftOffset=0¦BottomOffset=0¦Orientation=2¦PaperLength=1000¦PaperWidth=1000¦Scale=100¦PaperSource=15¦PrintQuality=600¦MediaType=1¦DitherType=10¦PaperKind=Letter¦PrintScaleMode=1
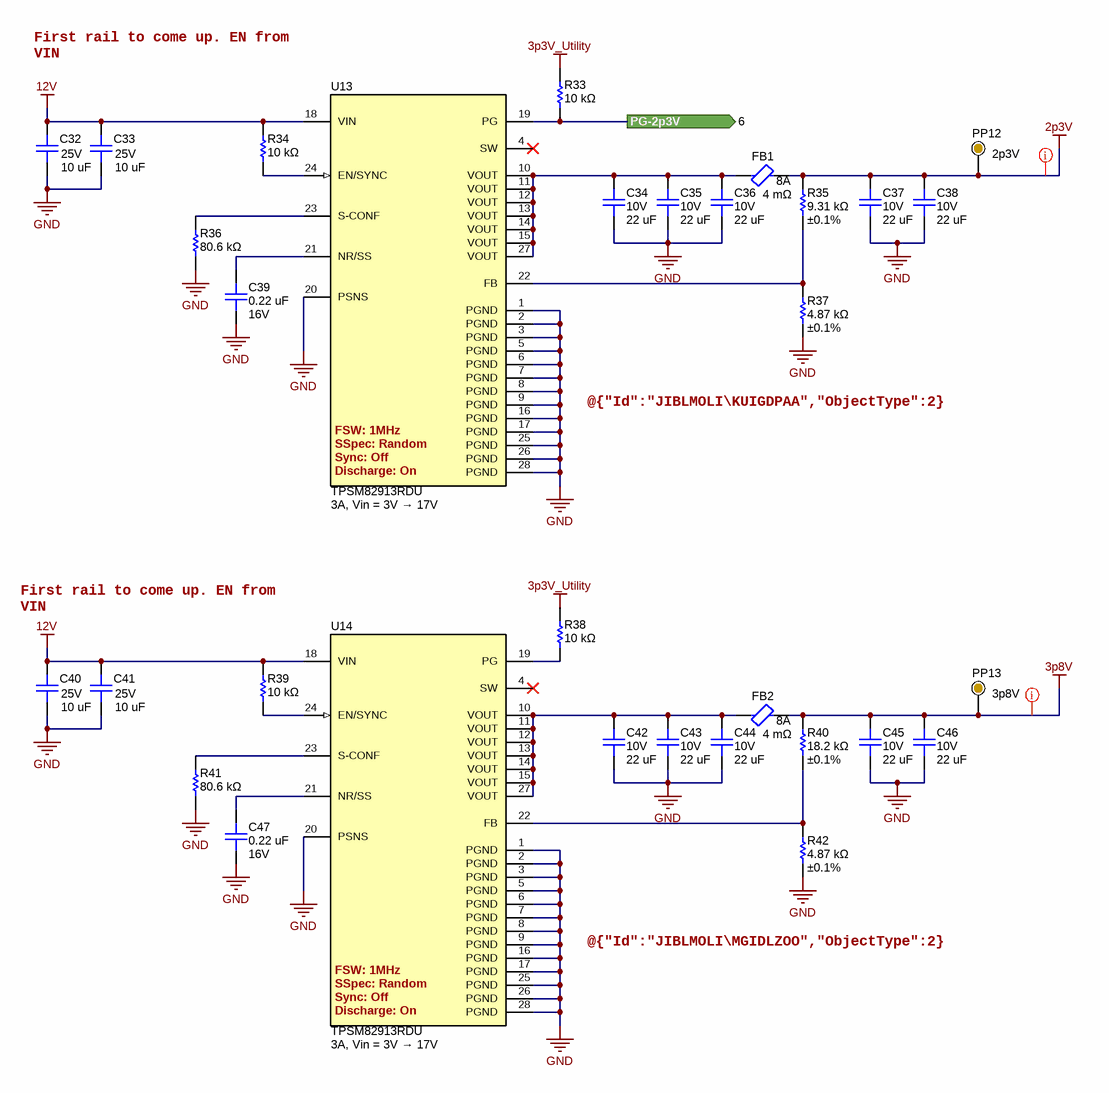
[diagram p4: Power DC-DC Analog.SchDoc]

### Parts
C32  value 10 uF  Voltage - Rated: 25V  [0805L_cap]  (hidden comment: C2012X7S1E106K125AC)
C33  value 10 uF  Voltage - Rated: 25V  [0805L_cap]  (hidden comment: C2012X7S1E106K125AC)
C34  value 22 uF  Voltage - Rated: 10V  [0805L_cap]  (hidden comment: C2012X7S1A226M125AC)
C35  value 22 uF  Voltage - Rated: 10V  [0805L_cap]  (hidden comment: C2012X7S1A226M125AC)
C36  value 22 uF  Voltage - Rated: 10V  [0805L_cap]  (hidden comment: C2012X7S1A226M125AC)
C37  value 22 uF  Voltage - Rated: 10V  [0805L_cap]  (hidden comment: C2012X7S1A226M125AC)
C38  value 22 uF  Voltage - Rated: 10V  [0805L_cap]  (hidden comment: C2012X7S1A226M125AC)
C39  value 0.22 uF  Voltage - Rated: 16V  [0402L_cap]  (hidden comment: CGA2B1X5R1C224M050BC)
C40  value 10 uF  Voltage - Rated: 25V  [0805L_cap]  (hidden comment: C2012X7S1E106K125AC)
C41  value 10 uF  Voltage - Rated: 25V  [0805L_cap]  (hidden comment: C2012X7S1E106K125AC)
C42  value 22 uF  Voltage - Rated: 10V  [0805L_cap]  (hidden comment: C2012X7S1A226M125AC)
C43  value 22 uF  Voltage - Rated: 10V  [0805L_cap]  (hidden comment: C2012X7S1A226M125AC)
C44  value 22 uF  Voltage - Rated: 10V  [0805L_cap]  (hidden comment: C2012X7S1A226M125AC)
C45  value 22 uF  Voltage - Rated: 10V  [0805L_cap]  (hidden comment: C2012X7S1A226M125AC)
C46  value 22 uF  Voltage - Rated: 10V  [0805L_cap]  (hidden comment: C2012X7S1A226M125AC)
C47  value 0.22 uF  Voltage - Rated: 16V  [0402L_cap]  (hidden comment: CGA2B1X5R1C224M050BC)
FB1  DCR: 4 mΩ  Current: 8A  [0603L]  (hidden comment: BLE18PS080SN1D)
FB2  DCR: 4 mΩ  Current: 8A  [0603L]  (hidden comment: BLE18PS080SN1D)
PP12  Text1: 2p3V  [ProbePoint_TH_40mil]  (hidden comment: Probe Point)  (no BOM)
PP13  Text1: 3p8V  [ProbePoint_TH_40mil]  (hidden comment: Probe Point)  (no BOM)
R33  value 10 kΩ  [0402L]  (hidden comment: ERJ-2RKF1002X)
R34  value 10 kΩ  [0402L]  (hidden comment: ERJ-2RKF1002X)
R35  value 9.31 kΩ  Tolerance: ±0.1%  [0402L]  (hidden comment: ERA-2AEB9311X)
R36  value 80.6 kΩ  [0402L]  (hidden comment: ERJ-2RKF8062X)
R37  value 4.87 kΩ  Tolerance: ±0.1%  [0402L]  (hidden comment: ERA-2AEB4871X)
R38  value 10 kΩ  [0402L]  (hidden comment: ERJ-2RKF1002X)
R39  value 10 kΩ  [0402L]  (hidden comment: ERJ-2RKF1002X)
R40  value 18.2 kΩ  Tolerance: ±0.1%  [0402L]  (hidden comment: ERA-2ARB1822X)
R41  value 80.6 kΩ  [0402L]  (hidden comment: ERJ-2RKF8062X)
R42  value 4.87 kΩ  Tolerance: ±0.1%  [0402L]  (hidden comment: ERA-2AEB4871X)
U13  TPSM82913RDU  Text1: 3A, Vin = 3V → 17V  Discharge: On  Sync: Off  SSpec: Random  FSW: 1MHz  [RDU0028A]
U14  TPSM82913RDU  Text1: 3A, Vin = 3V → 17V  Discharge: On  Sync: Off  SSpec: Random  FSW: 1MHz  [RDU0028A]

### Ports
PG-2p3V (out, see 6)

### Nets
2p3V: C37.2 C38.2 FB1.2 PP12.1 R35.2
3p3V_Utility: R33.2 R38.2
3p8V: C45.2 C46.2 FB2.2 PP13.1 R40.2
12V: C32.2 C33.2 C40.2 C41.2 R34.2 R39.2 U13.18(VIN) U14.18(VIN)
GND: C32.1 C33.1 C34.1 C35.1 C36.1 C37.1 C38.1 C39.2 C40.1 C41.1 C42.1 C43.1 C44.1 C45.1 C46.1 C47.2 R36.1 R37.1 R41.1 R42.1 U13.1(PGND) U13.2(PGND) U13.3(PGND) U13.5(PGND) U13.6(PGND) U13.7(PGND) U13.8(PGND) U13.9(PGND) U13.16(PGND) U13.17(PGND) U13.20(PSNS) U13.25(PGND) U13.26(PGND) U13.28(PGND) U14.1(PGND) U14.2(PGND) U14.3(PGND) U14.5(PGND) U14.6(PGND) U14.7(PGND) U14.8(PGND) U14.9(PGND) U14.16(PGND) U14.17(PGND) U14.20(PSNS) U14.25(PGND) U14.26(PGND) U14.28(PGND)
PG-2p3V: R33.1 U13.19(PG) ; port PG-2p3V
NetC34_2: C34.2 C35.2 C36.2 FB1.1 U13.10(VOUT) U13.11(VOUT) U13.12(VOUT) U13.13(VOUT) U13.14(VOUT) U13.15(VOUT) U13.27(VOUT)
NetC39_1: C39.1 U13.21(NR/SS)
NetC42_2: C42.2 C43.2 C44.2 FB2.1 U14.10(VOUT) U14.11(VOUT) U14.12(VOUT) U14.13(VOUT) U14.14(VOUT) U14.15(VOUT) U14.27(VOUT)
NetC47_1: C47.1 U14.21(NR/SS)
NetR34_1: R34.1 U13.24(EN/SYNC)
NetR35_1: R35.1 R37.2 U13.22(FB)
NetR36_2: R36.2 U13.23(S-CONF)
NetR38_1: R38.1 U14.19(PG)
NetR39_1: R39.1 U14.24(EN/SYNC)
NetR40_1: R40.1 R42.2 U14.22(FB)
NetR41_2: R41.2 U14.23(S-CONF)

Not connected (* = marked no-connect by the designer): U13 4(SW)*; U14 4(SW)*

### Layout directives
net class Power; net class GenPwr: 2p3V, 3p8V

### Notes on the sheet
- First rail to come up. EN from VIN
- @{"Id":"JIBLMOLI\KUIGDPAA","ObjectType":2} = @{"Id":"JIBLMOLI\VGZOEIJP","ObjectType":2} *(VOUT/0.8 -1)
- @{"Id":"JIBLMOLI\MGIDLZOO","ObjectType":2} = @{"Id":"JIBLMOLI\RDYCJVEF","ObjectType":2} *(VOUT/0.8 -1)

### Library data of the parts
C32 C33 C40 C41 = capcc03511: CAP CER 10UF 25V X7S 0805; Manufacturer: TDK Corporation; CompType: Capacitor Ceramic; Tolerance: ±10%; SizeX_mm: 2; SizeY_mm: 1.25; SizeZ_mm: 1.5
C34-C38 C42-C46 = capcc09395: as C9 on sheet 12V Input, Efuse and 3p3V Utility
C39 C47 = capcc01693: CAP CER 0.22UF 16V X5R 0402; Manufacturer: TDK Corporation; CompType: Capacitor Ceramic; Tolerance: ±20%; SizeX_mm: 1; SizeY_mm: 0.5; SizeZ_mm: 0.55
FB1 FB2 = dcp00004: 8.5 Ohms @ 100 MHz 1 Power Line Ferrite Bead 0603 (1608 Metric) 8A 4mOhm; Manufacturer: Murata; Impedance: 8.5 Ω; SizeX_mm: 1.6; SizeY_mm: 0.8
PP12 PP13 = cmp00025: Probe Point that can be used in lue of a test point
R33 R34 R38 R39 = RSMD040200314: as R5 on sheet 12V Input, Efuse and 3p3V Utility
R35 = RSMD040203923: RES SMD 9.31KOHM 0.1% 1/16W 0402; Manufacturer: Panasonic Electronic Components; CompType: Resistor SMD; Power (Watts): 0.063W, 1/16W; Temperature Coefficient: ±25ppm/°C; SizeX_mm: 1; SizeY_mm: 0.5; SizeZ_mm: 0.4
R36 R41 = RSMD040203748: RES SMD 80.6K OHM 1% 1/10W 0402; Manufacturer: Panasonic Electronic Components; CompType: Resistor SMD; Power (Watts): 0.1W, 1/10W; Temperature Coefficient: ±100ppm/°C; SizeX_mm: 1; SizeY_mm: 0.5; SizeZ_mm: 0.4
R37 R42 = RSMD040202615: RES SMD 4.87KOHM 0.1% 1/16W 0402; Manufacturer: Panasonic Electronic Components; CompType: Resistor SMD; Power (Watts): 0.063W, 1/16W; Temperature Coefficient: ±25ppm/°C; SizeX_mm: 1; SizeY_mm: 0.5; SizeZ_mm: 0.4
R40 = RSMD040201045: RES SMD 18.2KOHM 0.1% 1/16W 0402; Manufacturer: Panasonic Electronic Components; CompType: Resistor SMD; Power (Watts): 0.063W, 1/16W; Temperature Coefficient: ±10ppm/°C; SizeX_mm: 1; SizeY_mm: 0.5; SizeZ_mm: 0.4
U13 U14 = cmp00201: 3-V to 17-V, 3-A Low-Noise and Low-Ripple Buck Power Module with Integrated Ferrite Bead Filter Compensation; Part Number: TPSM82913RDUR; Manufacturer: Texas Instruments; Switching Frequency: 1/2.2MHz; Max Duty Cycle: 100%; Output Voltage: 0.8-5.5V; Standoff Height: 0mm; CompType: Switcher; Number Of Outputs: 1; Max Supply Voltage: 17V; AEC Category: Q200; TJmax_C: +125°C; Nominal Supply Current: 5mA; Output Type: AdjustableProgrammable; Min Supply Voltage: 3V; AEC Qualified: No

## Sheet Power LDO 1p8V Analog.SchDoc: DAC Analog 1.8V
size 431 x 279 mm; Date: Not shown in title block; ApprovedBy: Not shown in title block; CheckedBy: Not shown in title block; Author: Not shown in title block; CompanyName: Not shown in title block; Engineer: Not shown in title block; Organization: Not shown in title block; Address1: Not shown in title block; Address2: Not shown in title block; Address3: Not shown in title block; Address4: Not shown in title block; DocumentNumber: 1; Revision: Use project parameter SCH_Rev; SheetNumber: 6; SheetTotal: 21; PageSetup: Record=PageOptions¦CenterHorizontal=True¦CenterVertical=True¦PrintScale=1.00¦XCorrection=1.00¦YCorrection=1.00¦PrintKind=0¦BorderSize=5000000¦LeftOffset=0¦BottomOffset=0¦Orientation=2¦PaperLength=1000¦PaperWidth=1000¦Scale=100¦PaperSource=15¦PrintQuality=600¦MediaType=1¦DitherType=10¦PaperKind=Letter¦PrintScaleMode=1
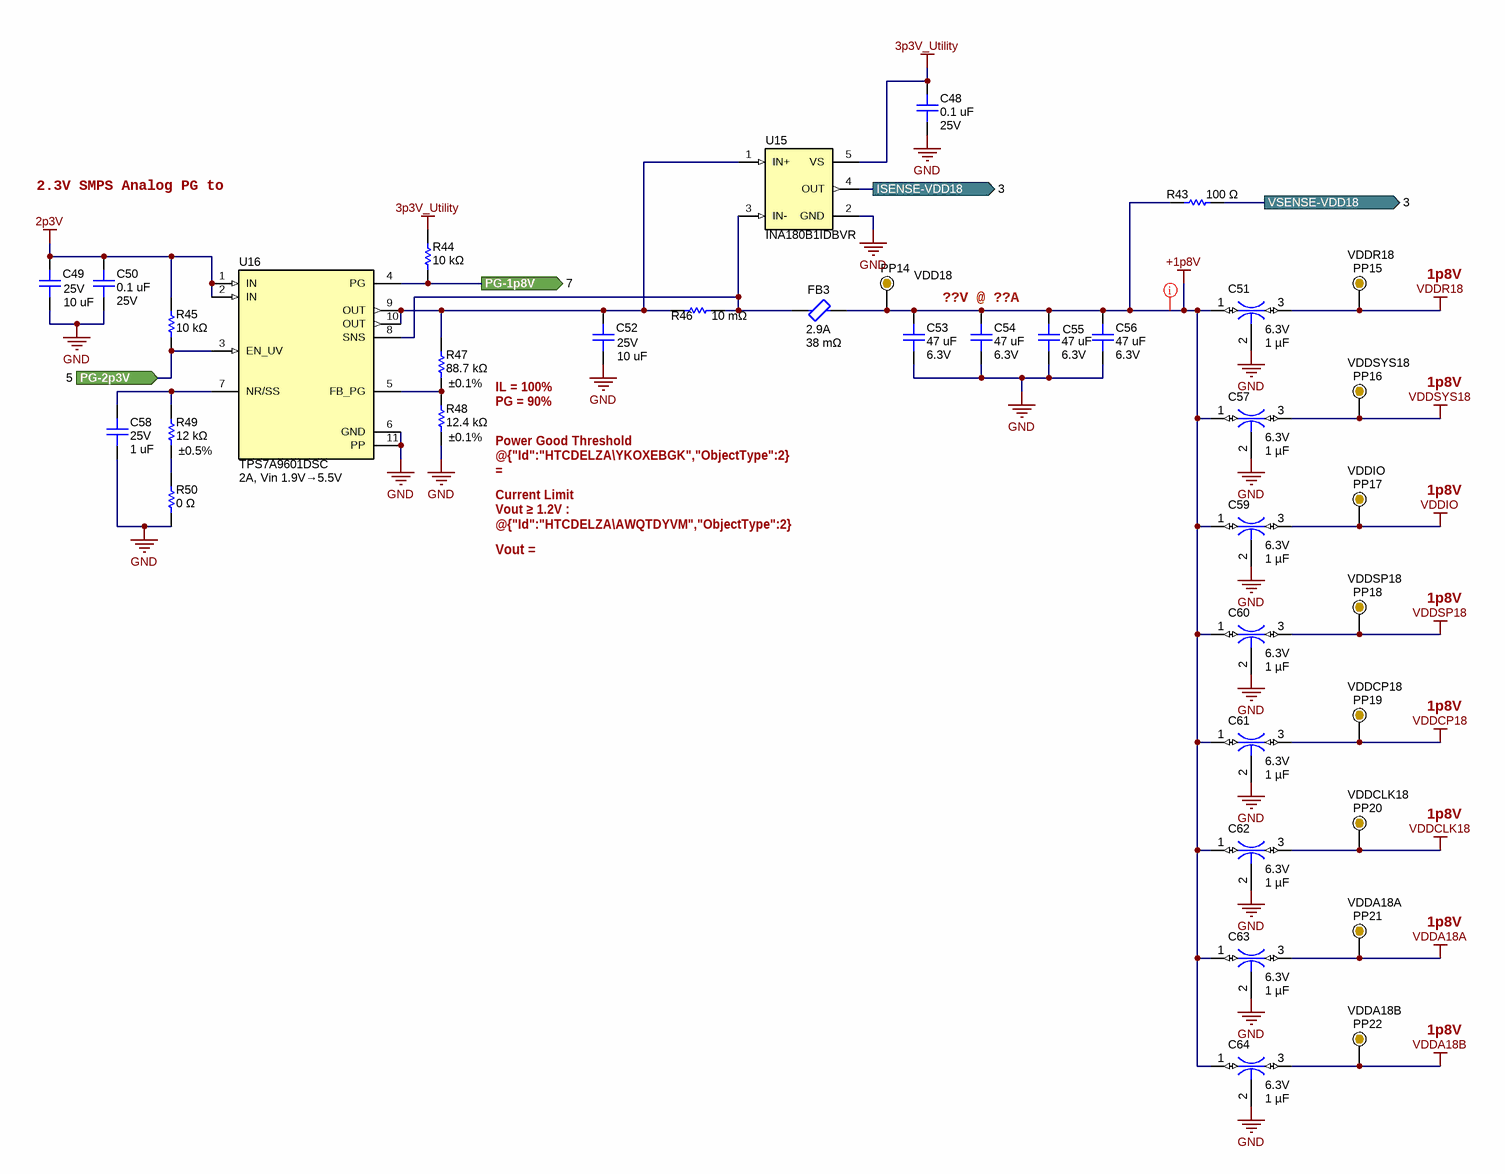
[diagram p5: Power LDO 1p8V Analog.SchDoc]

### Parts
C48  value 0.1 uF  Voltage - Rated: 25V  [0402L_cap]  (hidden comment: GRT155R71E104KE01J)
C49  value 10 uF  Voltage - Rated: 25V  [0805L_cap]  (hidden comment: C2012X7S1E106K125AC)
C50  value 0.1 uF  Voltage - Rated: 25V  [0402L_cap]  (hidden comment: GRT155R71E104KE01J)
C51  value 1 µF  Voltage - Rated: 6.3V  [NFM18PC]  (hidden comment: NFM18PC105R0J3D)
C52  value 10 uF  Voltage - Rated: 25V  [0805L_cap]  (hidden comment: C2012X7S1E106K125AC)
C53  value 47 uF  Voltage - Rated: 6.3V  [0603L_cap]  (hidden comment: GRM188R60J476ME15D)
C54  value 47 uF  Voltage - Rated: 6.3V  [0603L_cap]  (hidden comment: GRM188R60J476ME15D)
C55  value 47 uF  Voltage - Rated: 6.3V  [0603L_cap]  (hidden comment: GRM188R60J476ME15D)
C56  value 47 uF  Voltage - Rated: 6.3V  [0603L_cap]  (hidden comment: GRM188R60J476ME15D)
C57  value 1 µF  Voltage - Rated: 6.3V  [NFM18PC]  (hidden comment: NFM18PC105R0J3D)
C58  value 1 uF  Voltage - Rated: 25V  [0402L_cap]  (hidden comment: C1005X5R1E105K050BC)
C59  value 1 µF  Voltage - Rated: 6.3V  [NFM18PC]  (hidden comment: NFM18PC105R0J3D)
C60  value 1 µF  Voltage - Rated: 6.3V  [NFM18PC]  (hidden comment: NFM18PC105R0J3D)
C61  value 1 µF  Voltage - Rated: 6.3V  [NFM18PC]  (hidden comment: NFM18PC105R0J3D)
C62  value 1 µF  Voltage - Rated: 6.3V  [NFM18PC]  (hidden comment: NFM18PC105R0J3D)
C63  value 1 µF  Voltage - Rated: 6.3V  [NFM18PC]  (hidden comment: NFM18PC105R0J3D)
C64  value 1 µF  Voltage - Rated: 6.3V  [NFM18PC]  (hidden comment: NFM18PC105R0J3D)
FB3  Current: 2.9A  DCR: 38 mΩ  [1206L]  (hidden comment: BLM31KN601SN1L)
PP14  Text1: VDD18  [ProbePoint_TH_40mil]  (hidden comment: Probe Point)  (no BOM)
PP15  Text1: VDDR18  [ProbePoint_TH_40mil]  (hidden comment: Probe Point)  (no BOM)
PP16  Text1: VDDSYS18  [ProbePoint_TH_40mil]  (hidden comment: Probe Point)  (no BOM)
PP17  Text1: VDDIO  [ProbePoint_TH_40mil]  (hidden comment: Probe Point)  (no BOM)
PP18  Text1: VDDSP18  [ProbePoint_TH_40mil]  (hidden comment: Probe Point)  (no BOM)
PP19  Text1: VDDCP18  [ProbePoint_TH_40mil]  (hidden comment: Probe Point)  (no BOM)
PP20  Text1: VDDCLK18  [ProbePoint_TH_40mil]  (hidden comment: Probe Point)  (no BOM)
PP21  Text1: VDDA18A  [ProbePoint_TH_40mil]  (hidden comment: Probe Point)  (no BOM)
PP22  Text1: VDDA18B  [ProbePoint_TH_40mil]  (hidden comment: Probe Point)  (no BOM)
R43  value 100 Ω  [0201]  (hidden comment: ERJ-1GNF1000C)
R44  value 10 kΩ  [0402L]  (hidden comment: ERJ-2RKF1002X)
R45  value 10 kΩ  [0402L]  (hidden comment: ERJ-2RKF1002X)
R46  value 10 mΩ  [CCS0603FLxLxx]  (hidden comment: CSS0603FT10L0)
R47  value 88.7 kΩ  Tolerance: ±0.1%  [0402L]  (hidden comment: ERA-2AEB8872X)
R48  value 12.4 kΩ  Tolerance: ±0.1%  [0402L]  (hidden comment: ERA-2AEB1242X)
R49  value 12 kΩ  Tolerance: ±0.5%  [0402L]  (hidden comment: ERJ-U2RD1202X)
R50  value 0 Ω  [0402L]  (hidden comment: ERJ-U020R00X)
U15  INA180B1IDBVR  [DBV0005A]
U16  TPS7A9601DSC  Text1: 2A, Vin 1.9V→5.5V  [DRC0010J]

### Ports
ISENSE-VDD18 (out, see 3), PG-1p8V (out, see 7), PG-2p3V (in, see 5), VSENSE-VDD18 (out, see 3)

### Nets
2p3V: C49.2 C50.2 R45.2 U16.1(IN) U16.2(IN)
3p3V_Utility: C48.2 R44.2 U15.5(VS)
+1p8V: C51.1 C53.2 C54.2 C55.2 C56.2 C57.1 C59.1 C60.1 C61.1 C62.1 C63.1 C64.1 FB3.2 PP14.1 R43.1
GND: C48.1 C49.1 C50.1 C51.2 C52.1 C53.1 C54.1 C55.1 C56.1 C57.2 C58.1 C59.2 C60.2 C61.2 C62.2 C63.2 C64.2 R48.1 R50.1 U15.2(GND) U16.6(GND) U16.11(PP)
VDDA18A: C63.3 PP21.1
VDDA18B: C64.3 PP22.1
VDDCLK18: C62.3 PP20.1
VDDCP18: C61.3 PP19.1
VDDIO: C59.3 PP17.1
VDDR18: C51.3 PP15.1
VDDSP18: C60.3 PP18.1
VDDSYS18: C57.3 PP16.1
ISENSE-VDD18: U15.4(OUT) ; port ISENSE-VDD18
PG-1p8V: R44.1 U16.4(PG) ; port PG-1p8V
PG-2p3V: R45.1 U16.3(EN_UV) ; port PG-2p3V
VSENSE-VDD18: R43.2 ; port VSENSE-VDD18
NetC52_2: C52.2 R46.1 R47.2 U15.1(IN+) U16.9(OUT) U16.10(OUT)
NetC58_2: C58.2 R49.2 U16.7(NR/SS)
NetFB3_1: FB3.1 R46.2 U15.3(IN-) U16.8(SNS)
NetR47_1: R47.1 R48.2 U16.5(FB_PG)
NetR49_1: R49.1 R50.2

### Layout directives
net class Power; net class GenPwr: +1p8V

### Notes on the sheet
- 2.3V SMPS Analog PG to enable
- (near C54) ??V @ ??A
- 1p8V
- IL = 100%
  PG = 90%
- Power Good Threshold
  @{"Id":"HTCDELZA\YKOXEBGK","ObjectType":2} = @{"Id":"HTCDELZA\AWQTDYVM","ObjectType":2} * (VOUT/0.2*K-1)
  K = PG % Threshold
- Current Limit
  Vout ≥ 1.2V :    @{"Id":"HTCDELZA\AWQTDYVM","ObjectType":2} = 0.2V/16µA = 12.4kΩ
  0.4V≤Vout<1.2V : @{"Id":"HTCDELZA\AWQTDYVM","ObjectType":2} = 0.2V/6µA = 33.2k Ω
- Vout = (@{"Id":"HTCDELZA\DKKZNAKA","ObjectType":2} + @{"Id":"HTCDELZA\NXLNZVEN","ObjectType":2}) *150µA

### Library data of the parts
C48 C50 = capcc09401: as C19 on sheet Power DC-DC Digital
C49 C52 = capcc03511: as C32 on sheet Power DC-DC Analog
C51 C57 C59-C64 = dcp00009: CAP FEEDTHRU 1UF 20% 6.3V 0603; Manufacturer: Murata Electronics; CompType: Feed Thru Cap; Current: 4 A; DCR: 10 mΩ; SizeX_mm: 1.6; SizeY_mm: 0.8; SizeZ_mm: 0.7
C53-C56 = GRM188R60J476ME15D: CAP CER 47UF 6.3V X5R 0603; Manufacturer: Murata; CompType: Capacitor Ceramic; Tolerance: ±20%; SizeX_mm: 1.6; SizeY_mm: 0.81; SizeZ_mm: 0.9
C58 = CeramicCap: CAP CER 1UF 25V X5R 0402; Manufacturer: TDK Corporation; UniqueID: capcc02750; CompType: Capacitor Ceramic; Tolerance: ±10%; SizeX_mm: 1; SizeY_mm: 0.5; SizeZ_mm: 0.55
FB3 = dcp00613: FERRITE BEAD 600 OHM 1206 1LN; Manufacturer: Murata Electronics; Impedance: 600 Ω
PP14-PP22 = Probe Point: as PP1 on sheet 12V Input, Efuse and 3p3V Utility
R43 = RSMD020100289: as R12 on sheet Power Sense ADC
R44 R45 = RSMD040200314: as R5 on sheet 12V Input, Efuse and 3p3V Utility
R46 = OtherRs00003: RES 0.01 OHM 1% 1/3W 0603; Manufacturer: Stackpole Electronics Inc; CompType: Resistor SMD Sense; Power (Watts): 0.333W, 1/3W; Temperature Coefficient: ±50ppm/°C; SizeX_mm: 1.6; SizeY_mm: 0.8; SizeZ_mm: 0.65
R47 = RSMD040203878: RES SMD 88.7KOHM 0.1% 1/16W 0402; Manufacturer: Panasonic Electronic Components; CompType: Resistor SMD; Power (Watts): 0.063W, 1/16W; Temperature Coefficient: ±25ppm/°C; SizeX_mm: 1; SizeY_mm: 0.5; SizeZ_mm: 0.4
R48 = RSMD040200551: RES SMD 12.4KOHM 0.1% 1/16W 0402; Manufacturer: Panasonic Electronic Components; CompType: Resistor SMD; Power (Watts): 0.063W, 1/16W; Temperature Coefficient: ±25ppm/°C; SizeX_mm: 1; SizeY_mm: 0.5; SizeZ_mm: 0.4
R49 = Resistor: RES 12K OHM 0.5% 1/10W 0402 SMD; Manufacturer: Panasonic Electronic Components; UniqueID: RSMD040200530; CompType: Resistor SMD; Power (Watts): 0.1W, 1/10W; Temperature Coefficient: ±50ppm/°C; SizeX_mm: 1; SizeY_mm: 0.5; SizeZ_mm: 0.4
R50 = RSMD040200004: RES 0 OHM JUMPER 0402 SMD; Manufacturer: Panasonic Electronic Components; CompType: Resistor SMD; Power (Watts): 0.1W, 1/10W; Temperature Coefficient: -100/ +600ppm/°C; SizeX_mm: 1; SizeY_mm: 0.5; SizeZ_mm: 0.4
U15 = INA180B1IDBVR: as U9 on sheet Power DC-DC Digital
U16 = cmp00446: 2-A, ultra-low noise ultra-high PSRR RF voltage regulator; PartNumber: TPS7A9601DSCR; Manufacturer: Texas Instruments; CompType: LDO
